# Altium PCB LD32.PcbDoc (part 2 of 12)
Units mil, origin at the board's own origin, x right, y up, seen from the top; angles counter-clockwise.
Board outline 7007.87 x 4368.85 mil, 12 copper layers (Top Layer, Int1 (GND), Int2 (AVDD), Int3 (DVDD), Int4 (GND), Int5 (ST), Int6 (SB), Int8 (AGND), Int7 (AVCC), Int9 (VCCA), Int10 (GND), Bottom Layer), stack 60.136 mil thick; 1165 components, 667 nets, 3910 pads, 2570 vias.
Unrouted connection lines stored in the file: 14.
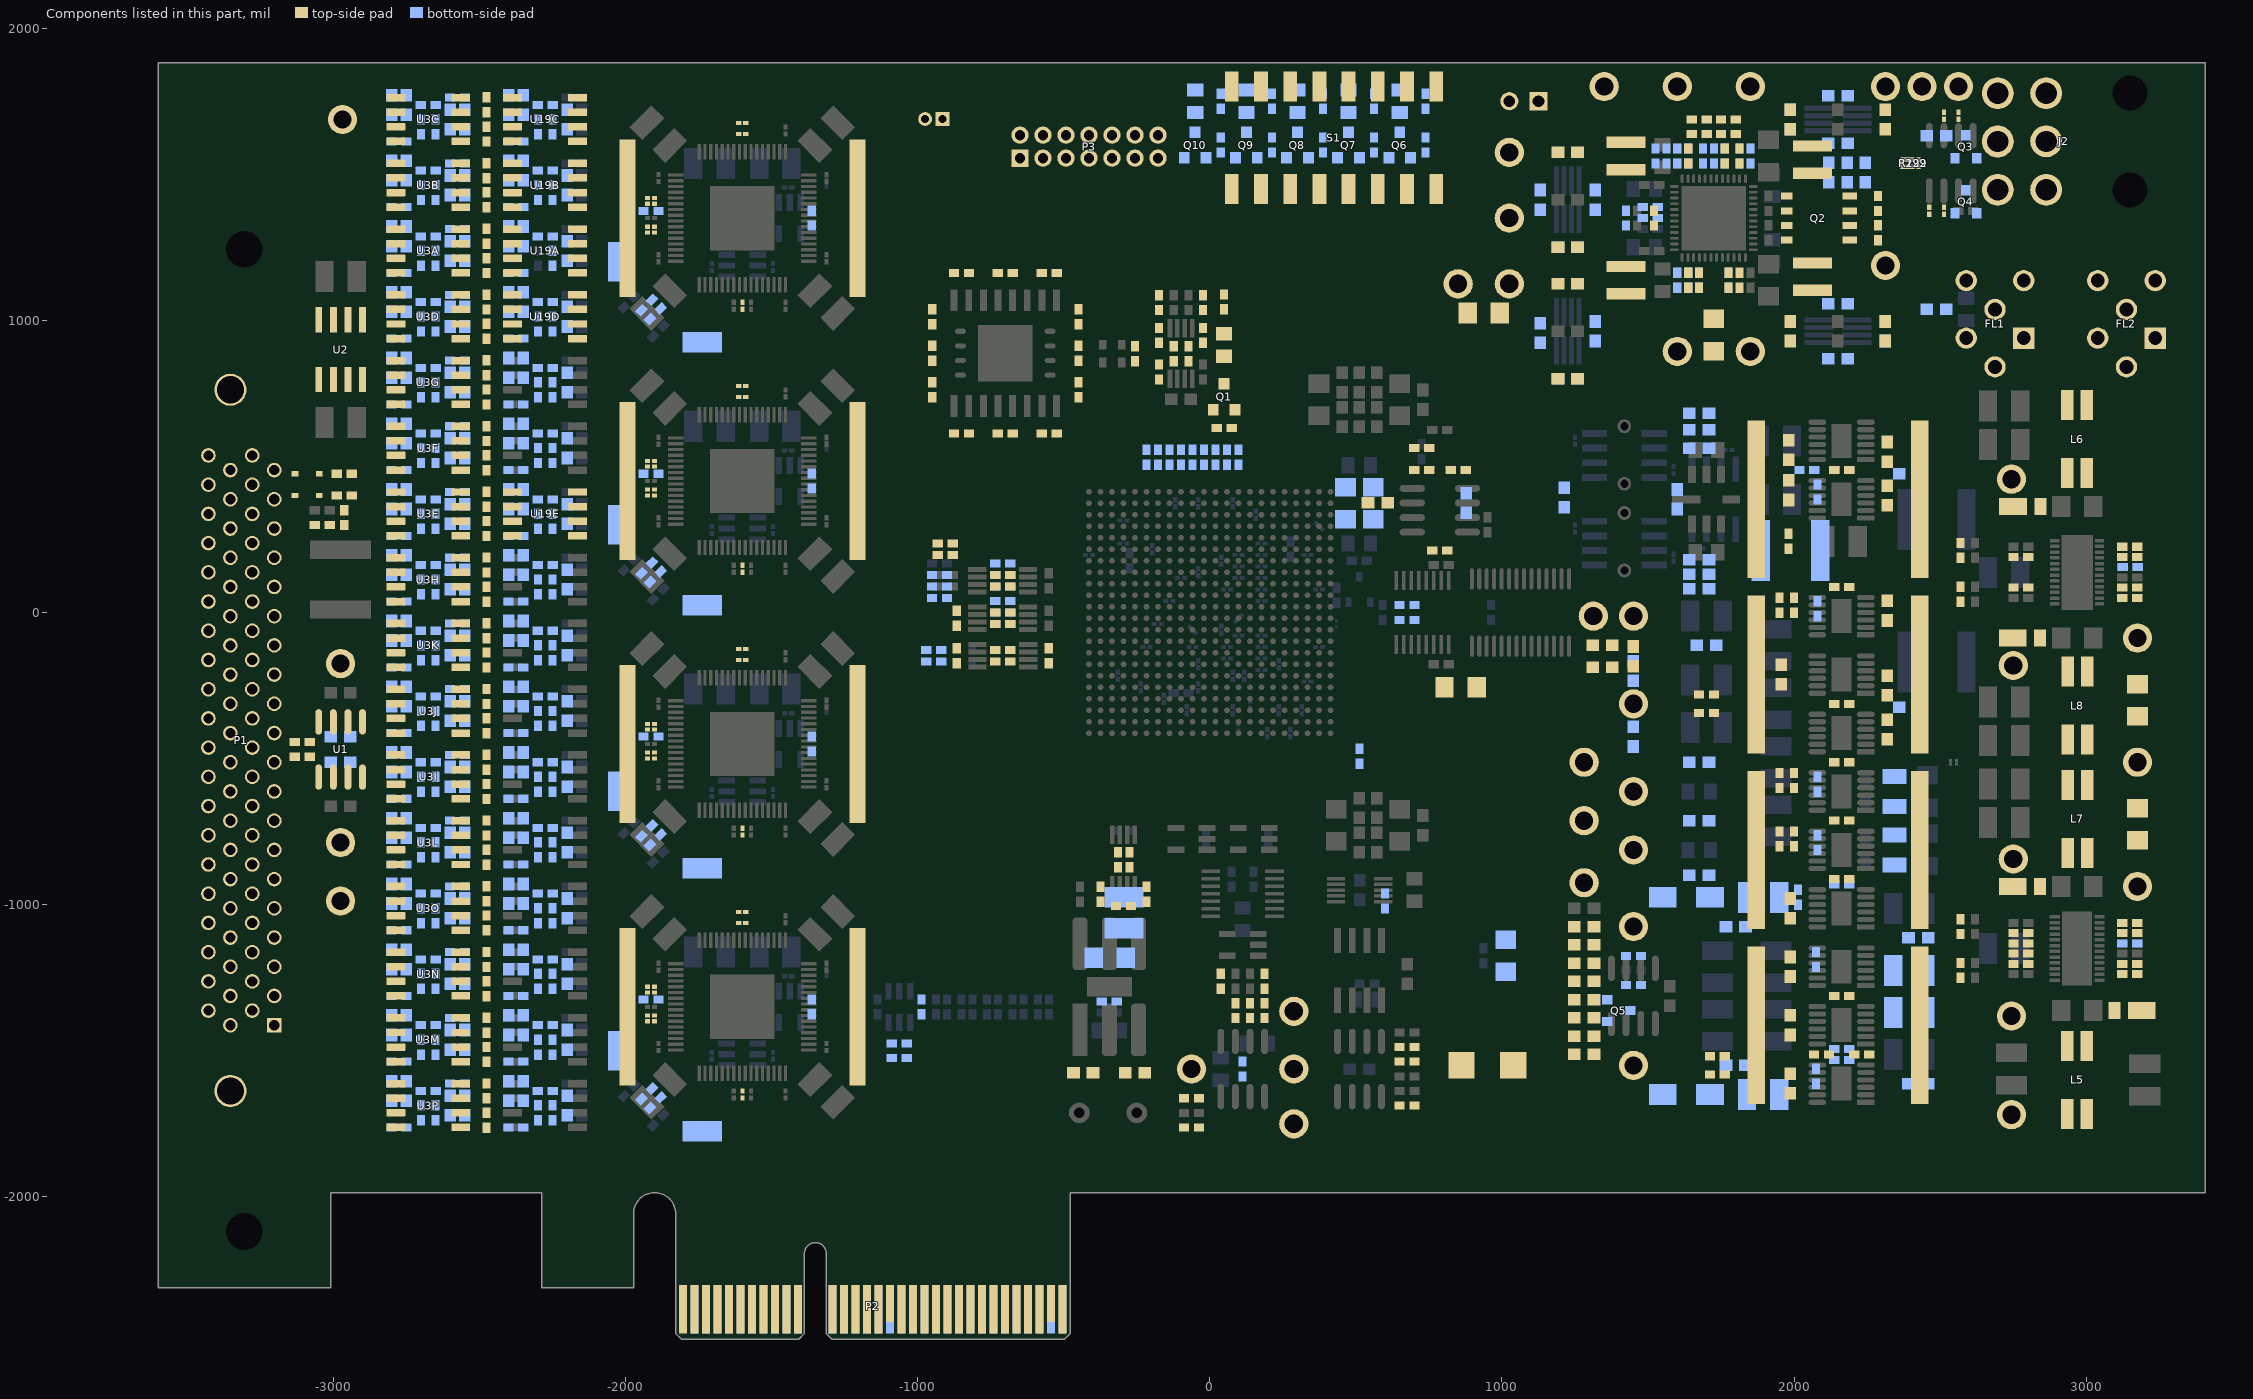
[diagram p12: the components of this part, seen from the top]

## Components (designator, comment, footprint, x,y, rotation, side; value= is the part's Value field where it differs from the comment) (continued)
C351B "NL" CC1005-0402 -2300,1437.5 r270 bottom locked (schematic designator C351)
C351C "NL" CC1005-0402 -2300,1662.5 r270 bottom locked (schematic designator C351)
C351D "NL" CC1005-0402 -2300,987.5 r270 bottom locked (schematic designator C351)
C351E "NL" CC1005-0402 -2300,312.5 r270 bottom locked (schematic designator C351)
C351F "NL" CC1005-0402 -2300,537.5 r270 bottom locked (schematic designator C351)
C351G "NL" CC1005-0402 -2300,762.5 r270 bottom locked (schematic designator C351)
C351H "NL" CC1005-0402 -2300,87.5 r270 bottom locked (schematic designator C351)
C351I "NL" CC1005-0402 -2300,-587.5 r270 bottom locked (schematic designator C351)
C351J "NL" CC1005-0402 -2300,-362.5 r270 bottom locked (schematic designator C351)
C351K "NL" CC1005-0402 -2300,-137.5 r270 bottom locked (schematic designator C351)
C351L "NL" CC1005-0402 -2300,-812.5 r270 bottom locked (schematic designator C351)
C351M "NL" CC1005-0402 -2300,-1487.5 r270 bottom locked (schematic designator C351)
C351N "NL" CC1005-0402 -2300,-1262.5 r270 bottom locked (schematic designator C351)
C351O "NL" CC1005-0402 -2300,-1037.5 r270 bottom locked (schematic designator C351)
C351P "NL" CC1005-0402 -2300,-1712.5 r270 bottom locked (schematic designator C351)
C367A "100nF" CC1005-0402 -2375,1162.5 r0 bottom locked (schematic designator C367)
C367B "100nF" CC1005-0402 -2375,1387.5 r0 bottom locked (schematic designator C367)
C367C "100nF" CC1005-0402 -2375,1612.5 r0 bottom locked (schematic designator C367)
C367D "100nF" CC1005-0402 -2375,937.5 r0 bottom locked (schematic designator C367)
C367E "100nF" CC1005-0402 -2375,262.5 r0 bottom locked (schematic designator C367)
C367F "100nF" CC1005-0402 -2375,487.5 r0 bottom locked (schematic designator C367)
C367G "100nF" CC1005-0402 -2375,712.5 r0 bottom locked (schematic designator C367)
C367H "100nF" CC1005-0402 -2375,37.5 r0 bottom locked (schematic designator C367)
C367I "100nF" CC1005-0402 -2375,-637.5 r0 bottom locked (schematic designator C367)
C367J "100nF" CC1005-0402 -2375,-412.5 r0 bottom locked (schematic designator C367)
C367K "100nF" CC1005-0402 -2375,-187.5 r0 bottom locked (schematic designator C367)
C367L "100nF" CC1005-0402 -2375,-862.5 r0 bottom locked (schematic designator C367)
C367M "100nF" CC1005-0402 -2375,-1537.5 r0 bottom locked (schematic designator C367)
C367N "100nF" CC1005-0402 -2375,-1312.5 r0 bottom locked (schematic designator C367)
C367O "100nF" CC1005-0402 -2375,-1087.5 r0 bottom locked (schematic designator C367)
C367P "100nF" CC1005-0402 -2375,-1762.5 r0 bottom locked (schematic designator C367)
C383A "2.2nF" CC1608-0603 -2400,1287.5 r270 bottom locked (schematic designator C383)
C383B "2.2nF" CC1608-0603 -2400,1512.5 r270 bottom locked (schematic designator C383)
C383C "2.2nF" CC1608-0603 -2400,1737.5 r270 bottom locked (schematic designator C383)
C383D "2.2nF" CC1608-0603 -2400,1062.5 r270 bottom locked (schematic designator C383)
C383E "2.2nF" CC1608-0603 -2400,387.5 r270 bottom locked (schematic designator C383)
C383F "2.2nF" CC1608-0603 -2400,612.5 r270 bottom locked (schematic designator C383)
C383G "2.2nF" CC1608-0603 -2400,837.5 r270 bottom locked (schematic designator C383)
C383H "2.2nF" CC1608-0603 -2400,162.5 r270 bottom locked (schematic designator C383)
C383I "2.2nF" CC1608-0603 -2400,-512.5 r270 bottom locked (schematic designator C383)
C383J "2.2nF" CC1608-0603 -2400,-287.5 r270 bottom locked (schematic designator C383)
C383K "2.2nF" CC1608-0603 -2400,-62.5 r270 bottom locked (schematic designator C383)
C383L "2.2nF" CC1608-0603 -2400,-737.5 r270 bottom locked (schematic designator C383)
C383M "2.2nF" CC1608-0603 -2400,-1412.5 r270 bottom locked (schematic designator C383)
C383N "2.2nF" CC1608-0603 -2400,-1187.5 r270 bottom locked (schematic designator C383)
C383O "2.2nF" CC1608-0603 -2400,-962.5 r270 bottom locked (schematic designator C383)
C383P "2.2nF" CC1608-0603 -2400,-1637.5 r270 bottom locked (schematic designator C383)
C399A "2.2nF" CC1608-0603 -2550,1237.5 r270 bottom locked (schematic designator C399)
C399B "2.2nF" CC1608-0603 -2550,1462.5 r270 bottom locked (schematic designator C399)
C399C "2.2nF" CC1608-0603 -2550,1687.5 r270 bottom locked (schematic designator C399)
C399D "2.2nF" CC1608-0603 -2550,1012.5 r270 bottom locked (schematic designator C399)
C399E "2.2nF" CC1608-0603 -2550,337.5 r270 bottom locked (schematic designator C399)
C399F "2.2nF" CC1608-0603 -2550,562.5 r270 bottom locked (schematic designator C399)
C399G "2.2nF" CC1608-0603 -2550,787.5 r270 bottom locked (schematic designator C399)
C399H "2.2nF" CC1608-0603 -2550,112.5 r270 bottom locked (schematic designator C399)
C399I "2.2nF" CC1608-0603 -2550,-562.5 r270 bottom locked (schematic designator C399)
C399J "2.2nF" CC1608-0603 -2550,-337.5 r270 bottom locked (schematic designator C399)
C399K "2.2nF" CC1608-0603 -2550,-112.5 r270 bottom locked (schematic designator C399)
C399L "2.2nF" CC1608-0603 -2550,-787.5 r270 bottom locked (schematic designator C399)
C399M "2.2nF" CC1608-0603 -2550,-1462.5 r270 bottom locked (schematic designator C399)
C399N "2.2nF" CC1608-0603 -2550,-1237.5 r270 bottom locked (schematic designator C399)
C399O "2.2nF" CC1608-0603 -2550,-1012.5 r270 bottom locked (schematic designator C399)
C399P "2.2nF" CC1608-0603 -2550,-1687.5 r270 bottom locked (schematic designator C399)
C415A "100nF" CC1005-0402 -2575,1312.5 r180 bottom locked (schematic designator C415)
C415B "100nF" CC1005-0402 -2575,1537.5 r180 bottom locked (schematic designator C415)
C415C "100nF" CC1005-0402 -2575,1762.5 r180 bottom locked (schematic designator C415)
C415D "100nF" CC1005-0402 -2575,1087.5 r180 bottom locked (schematic designator C415)
C415E "100nF" CC1005-0402 -2575,412.5 r180 bottom locked (schematic designator C415)
C415F "100nF" CC1005-0402 -2575,637.5 r180 bottom locked (schematic designator C415)
C415G "100nF" CC1005-0402 -2575,862.5 r180 bottom locked (schematic designator C415)
C415H "100nF" CC1005-0402 -2575,187.5 r180 bottom locked (schematic designator C415)
C415I "100nF" CC1005-0402 -2575,-487.5 r180 bottom locked (schematic designator C415)
C415J "100nF" CC1005-0402 -2575,-262.5 r180 bottom locked (schematic designator C415)
C415K "100nF" CC1005-0402 -2575,-37.5 r180 bottom locked (schematic designator C415)
C415L "100nF" CC1005-0402 -2575,-712.5 r180 bottom locked (schematic designator C415)
C415M "100nF" CC1005-0402 -2575,-1387.5 r180 bottom locked (schematic designator C415)
C415N "100nF" CC1005-0402 -2575,-1162.5 r180 bottom locked (schematic designator C415)
C415O "100nF" CC1005-0402 -2575,-937.5 r180 bottom locked (schematic designator C415)
C415P "100nF" CC1005-0402 -2575,-1612.5 r180 bottom locked (schematic designator C415)
C431A "NL" CC1005-0402 -2700,1212.5 r270 bottom locked (schematic designator C431)
C431B "NL" CC1005-0402 -2700,1437.5 r270 bottom locked (schematic designator C431)
C431C "NL" CC1005-0402 -2700,1662.5 r270 bottom locked (schematic designator C431)
C431D "NL" CC1005-0402 -2700,987.5 r270 bottom locked (schematic designator C431)
C431E "NL" CC1005-0402 -2700,312.5 r270 bottom locked (schematic designator C431)
C431F "NL" CC1005-0402 -2700,537.5 r270 bottom locked (schematic designator C431)
C431G "NL" CC1005-0402 -2700,762.5 r270 bottom locked (schematic designator C431)
C431H "NL" CC1005-0402 -2700,87.5 r270 bottom locked (schematic designator C431)
C431I "NL" CC1005-0402 -2700,-587.5 r270 bottom locked (schematic designator C431)
C431J "NL" CC1005-0402 -2700,-362.5 r270 bottom locked (schematic designator C431)
C431K "NL" CC1005-0402 -2700,-137.5 r270 bottom locked (schematic designator C431)
C431L "NL" CC1005-0402 -2700,-812.5 r270 bottom locked (schematic designator C431)
C431M "NL" CC1005-0402 -2700,-1487.5 r270 bottom locked (schematic designator C431)
C431N "NL" CC1005-0402 -2700,-1262.5 r270 bottom locked (schematic designator C431)
C431O "NL" CC1005-0402 -2700,-1037.5 r270 bottom locked (schematic designator C431)
C431P "NL" CC1005-0402 -2700,-1712.5 r270 bottom locked (schematic designator C431)
C447A "100nF" CC1005-0402 -2775,1162.5 r0 bottom locked (schematic designator C447)
C447B "100nF" CC1005-0402 -2775,1387.5 r0 bottom locked (schematic designator C447)
C447C "100nF" CC1005-0402 -2775,1612.5 r0 bottom locked (schematic designator C447)
C447D "100nF" CC1005-0402 -2775,937.5 r0 bottom locked (schematic designator C447)
C447E "100nF" CC1005-0402 -2775,262.5 r0 bottom locked (schematic designator C447)
C447F "100nF" CC1005-0402 -2775,487.5 r0 bottom locked (schematic designator C447)
C447G "100nF" CC1005-0402 -2775,712.5 r0 bottom locked (schematic designator C447)
C447H "100nF" CC1005-0402 -2775,37.5 r0 bottom locked (schematic designator C447)
C447I "100nF" CC1005-0402 -2775,-637.5 r0 bottom locked (schematic designator C447)
C447J "100nF" CC1005-0402 -2775,-412.5 r0 bottom locked (schematic designator C447)
C447K "100nF" CC1005-0402 -2775,-187.5 r0 bottom locked (schematic designator C447)
C447L "100nF" CC1005-0402 -2775,-862.5 r0 bottom locked (schematic designator C447)
C447M "100nF" CC1005-0402 -2775,-1537.5 r0 bottom locked (schematic designator C447)
C447N "100nF" CC1005-0402 -2775,-1312.5 r0 bottom locked (schematic designator C447)
C447O "100nF" CC1005-0402 -2775,-1087.5 r0 bottom locked (schematic designator C447)
C447P "100nF" CC1005-0402 -2775,-1762.5 r0 bottom locked (schematic designator C447)
C463A "2.2nF" CC1608-0603 -2800,1287.5 r270 bottom locked (schematic designator C463)
C463B "2.2nF" CC1608-0603 -2800,1512.5 r270 bottom locked (schematic designator C463)
C463C "2.2nF" CC1608-0603 -2800,1737.5 r270 bottom locked (schematic designator C463)
C463D "2.2nF" CC1608-0603 -2800,1062.5 r270 bottom locked (schematic designator C463)
C463E "2.2nF" CC1608-0603 -2800,387.5 r270 bottom locked (schematic designator C463)
C463F "2.2nF" CC1608-0603 -2800,612.5 r270 bottom locked (schematic designator C463)
C463G "2.2nF" CC1608-0603 -2800,837.5 r270 bottom locked (schematic designator C463)
C463H "2.2nF" CC1608-0603 -2800,162.5 r270 bottom locked (schematic designator C463)
C463I "2.2nF" CC1608-0603 -2800,-512.5 r270 bottom locked (schematic designator C463)
C463J "2.2nF" CC1608-0603 -2800,-287.5 r270 bottom locked (schematic designator C463)
C463K "2.2nF" CC1608-0603 -2800,-62.5 r270 bottom locked (schematic designator C463)
C463L "2.2nF" CC1608-0603 -2800,-737.5 r270 bottom locked (schematic designator C463)
C463M "2.2nF" CC1608-0603 -2800,-1412.5 r270 bottom locked (schematic designator C463)
C463N "2.2nF" CC1608-0603 -2800,-1187.5 r270 bottom locked (schematic designator C463)
C463O "2.2nF" CC1608-0603 -2800,-962.5 r270 bottom locked (schematic designator C463)
C463P "2.2nF" CC1608-0603 -2800,-1637.5 r270 bottom locked (schematic designator C463)
C479 "1.0uF" CC1608-0603 -2975,-425 r180 bottom
C480 "1.0uF" CC1608-0603 -2975,-512.5 r0 bottom
C481 "10uF" CC3225-1210 1893.75,-1650 r180 bottom value=10uf
C482 "10uF" CC3225-1210 1893.75,-975 r0 bottom value=10uf
C483 "10uF" CC3225-1210 2393.75,-1368.75 r180 bottom value=10uf
C484 "10uF" CC3225-1210 2393.75,-1225 r0 bottom value=10uf
C500 "22uF" CC5650-2220 1987.5,212.5 r0 bottom value="22uF Film"
D1 "BAV116WSQ-7" FP-SOD323-MFG -3090,400 r0 top value=1.5pF
D2 "BAV116WSQ-7" FP-SOD323-MFG -3090,475 r180 top value=1.5pF
D3 "Schottky SMB" DO-SMB 950,-1550 r0 top
D4 "Schottky DO-PowerDI123" DO-PowerDI123 2781.25,-937.5 r180 top
D5 "Schottky DO-PowerDI123" DO-PowerDI123 2781.25,-87.5 r180 top
D6 "Schottky DO-PowerDI123" DO-PowerDI123 2782.5,362.5 r180 top
D7 "Schottky DO-PowerDI123" DO-PowerDI123 3156.25,-1362.5 r0 top
D8 "shottky diode" DO-SMA 1631.25,-975 r180 bottom
D9 "shottky diode" DO-SMA 1631.25,-1650 r0 bottom
DS1 "DONE" LED-0805 49.21,915.35 r90 top
DS2 "LED" LED-0805 650,1750 r90 bottom
DS3 "LED" LED-0805 475,1750 r90 bottom
DS4 "LED" LED-0805 300,1750 r90 bottom
DS5 "LED" LED-0805 125,1750 r90 bottom
DS6 "LED" LED-0805 -50,1750 r90 bottom
FL1 "BNX016-01" FP-BNX_L12MM2_W11MM2_T8MM-MFG 2687.5,1037.5 r270 top
FL2 "BNX016-01" FP-BNX_L12MM2_W11MM2_T8MM-MFG 3137.5,1037.5 r270 top
FR1 "BLM31PG121" CC3216-1206 858.27,-255.91 r0 top
FR2 "BLM31PG121" CC3216-1206 937.5,1025 r180 top
FR3 "BLM31PG121" CC3216-1206 1725,950 r270 top
FR4 "BLM31PG121" CC3216-1206 3175,-725 r270 top
FR5 "BLM31PG121" CC3216-1206 3175,-300 r90 top
FR6 "BLM31PG121" CC3216-1206 1012.5,-1175 r90 bottom
FR7 "BLM31PG121" CC3216-1206 559.06,374.02 r270 bottom
FR8 "BLM31PG121" CC3216-1206 464.57,374.02 r270 bottom
FR9 "BLM31PG121" CC3216-1206 -342.5,-1181.25 r0 bottom
J1 "S2B-ZR(LF)(SN)" FP-S2B-ZR_LF_SN-MFG -944.88,1751.97 r180 top
J2 "45558-0003" 455580003 2862.5,1777.5 r270 top
L1 "XFL4020-222MEC" FP-XFL4020-MFG 1425,1137.5 r270 top
L2 "XFL4020-222MEC" FP-XFL4020-MFG 1425,1562.5 r90 top
L3 "XFL4020-332MEC" FP-XFL4020-MFG 2062.5,1150 r270 top
L4 "XFL4020-472" FP-XAL40-MFG 2062.5,1550 r90 top value=4.7uH
L5 "8.2uH" MSD7342 2935.25,-1493.5 r0 top
L6 "8.2uH" MSD7342 3002.25,487.25 r180 top
L7 "8.2uH" MSD7342 3002.75,-812.75 r180 top
L8 "4.7uH" MSD7342 2935.75,-212.25 r0 top
L9 "33nH" CL2520-1008 2343.75,-812.5 r270 bottom
L10 "33nH" CL2520-1008 2343.75,-612.5 r270 bottom
LOGO1 "LIGO logo" LIGO-LOGO-SM -3415,1728.75 r0 top value=NL
MP4A "DA-T268-301E-TR" FP-DA-T268-301E-TR-MFG -1600,-1350 r0 top locked (schematic designator MP4)
MP4B "DA-T268-301E-TR" FP-DA-T268-301E-TR-MFG -1600,-450 r0 top locked (schematic designator MP4)
MP4C "DA-T268-301E-TR" FP-DA-T268-301E-TR-MFG -1600,450 r0 top locked (schematic designator MP4)
MP4D "DA-T268-301E-TR" FP-DA-T268-301E-TR-MFG -1600,1350 r0 top locked (schematic designator MP4)
MP5 "DA-T263-201E-TR" FP-DA-T263-201E-TR-MFG 2150,-1412.5 r0 top locked
MP6 "DA-T263-201E-TR" FP-DA-T263-201E-TR-MFG 2150,-812.5 r0 top
MP7 "DA-T263-201E-TR" FP-DA-T263-201E-TR-MFG 2150,-212.5 r0 top locked
MP8 "DA-T263-201E-TR" FP-DA-T263-201E-TR-MFG 2150,387.5 r0 top locked
P1 "P50E-080P1-RR1EA" P50E-080-SR1 -3302.3,-1437.5 r270 top locked
P2 "PCIeX4-GF-2D-1000-1K-O64" PCIeX4-GF-2D-1000-1K-O64 -1429.06,-2385 r0 top value=NL
P3 "2mm Header 2x7" 2MM_HDR2X7_RA -649.61,1555.12 r0 top
P4 "Header 2" WM4200 1125,1750 r180 top
Q1 "FDV301N" SO-G3/C2.25 49.21,738.19 r0 top
Q2 "SI7904BDN-T1-E3" VISH-POWERPAKSO-8_A_V 2085.04,1350 r180 top
Q3 "MMBT3906LT1G" ONSC-SOT-23-3-318-08_V 2587.5,1593.75 r90 bottom
Q4 "MMBT3906LT1G" ONSC-SOT-23-3-318-08_V 2587.5,1406.25 r90 bottom
Q5 "MMBT3906LT1G" ONSC-SOT-23-3-318-08_V 1400,-1362.5 r0 bottom
Q6 "FDV301N" SO-G3/C2.25 650,1600 r180 bottom
Q7 "FDV301N" SO-G3/C2.25 475,1600 r180 bottom
Q8 "FDV301N" SO-G3/C2.25 300,1600 r180 bottom
Q9 "FDV301N" SO-G3/C2.25 125,1600 r180 bottom
Q10 "FDV301N" SO-G3/C2.25 -50,1600 r180 bottom
R1 "100" CR1005-0402 -3106.25,-493.75 r180 top
R2 "100" CR1005-0402 -3106.25,-443.75 r180 top
R3 "10k" CR1005-0402 -3037.5,300 r180 top
R4 "1.33k" CR1005-0402 -2962.5,400 r180 top
R5 "13.3k" CR1005-0402 -2962.5,475 r180 top
R6 "1.0k" CR1005-0402 -2962.5,325 r90 top
R7A "NL" CR1005-0402 -2475,1187.5 r270 top locked (schematic designator R7)
R7B "NL" CR1005-0402 -2475,1412.5 r270 top locked (schematic designator R7)
R7C "NL" CR1005-0402 -2475,1637.5 r270 top locked (schematic designator R7)
R7D "NL" CR1005-0402 -2475,962.5 r270 top locked (schematic designator R7)
R7E "NL" CR1005-0402 -2475,287.5 r270 top locked (schematic designator R7)
R7F "NL" CR1005-0402 -2475,512.5 r270 top locked (schematic designator R7)
R7G "NL" CR1005-0402 -2475,737.5 r270 top locked (schematic designator R7)
R7H "NL" CR1005-0402 -2475,62.5 r270 top locked (schematic designator R7)
R7I "NL" CR1005-0402 -2475,-612.5 r270 top locked (schematic designator R7)
R7J "NL" CR1005-0402 -2475,-387.5 r270 top locked (schematic designator R7)
R7K "NL" CR1005-0402 -2475,-162.5 r270 top locked (schematic designator R7)
R7L "NL" CR1005-0402 -2475,-837.5 r270 top locked (schematic designator R7)
R7M "NL" CR1005-0402 -2475,-1512.5 r270 top locked (schematic designator R7)
R7N "NL" CR1005-0402 -2475,-1287.5 r270 top locked (schematic designator R7)
R7O "NL" CR1005-0402 -2475,-1062.5 r270 top locked (schematic designator R7)
R7P "NL" CR1005-0402 -2475,-1737.5 r270 top locked (schematic designator R7)
R8A "NL" CR1005-0402 -2475,1287.5 r270 top locked (schematic designator R8)
R8B "NL" CR1005-0402 -2475,1512.5 r270 top locked (schematic designator R8)
R8C "NL" CR1005-0402 -2475,1737.5 r270 top locked (schematic designator R8)
R8D "NL" CR1005-0402 -2475,1062.5 r270 top locked (schematic designator R8)
R8E "NL" CR1005-0402 -2475,387.5 r270 top locked (schematic designator R8)
R8F "NL" CR1005-0402 -2475,612.5 r270 top locked (schematic designator R8)
R8G "NL" CR1005-0402 -2475,837.5 r270 top locked (schematic designator R8)
R8H "NL" CR1005-0402 -2475,162.5 r270 top locked (schematic designator R8)
R8I "NL" CR1005-0402 -2475,-512.5 r270 top locked (schematic designator R8)
R8J "NL" CR1005-0402 -2475,-287.5 r270 top locked (schematic designator R8)
R8K "NL" CR1005-0402 -2475,-62.5 r270 top locked (schematic designator R8)
R8L "NL" CR1005-0402 -2475,-737.5 r270 top locked (schematic designator R8)
R8M "NL" CR1005-0402 -2475,-1412.5 r270 top locked (schematic designator R8)
R8N "NL" CR1005-0402 -2475,-1187.5 r270 top locked (schematic designator R8)
R8O "NL" CR1005-0402 -2475,-962.5 r270 top locked (schematic designator R8)
R8P "NL" CR1005-0402 -2475,-1637.5 r270 top locked (schematic designator R8)
R39A "47K" CR0603-0201 -1912.5,1300.79 r180 top locked (schematic designator R39)
R39B "47K" CR0603-0201 -1912.5,400.79 r180 top locked (schematic designator R39)
R39C "47K" CR0603-0201 -1912.5,-499.21 r180 top locked (schematic designator R39)
R39D "47K" CR0603-0201 -1912.5,-1399.21 r180 top locked (schematic designator R39)
R40A "47K" CR0603-0201 -1912.5,1320.47 r180 top locked (schematic designator R40)
R40B "47K" CR0603-0201 -1912.5,420.47 r180 top locked (schematic designator R40)
R40C "47K" CR0603-0201 -1912.5,-479.53 r180 top locked (schematic designator R40)
R40D "47K" CR0603-0201 -1912.5,-1379.53 r180 top locked (schematic designator R40)
R41A "2k" CR0603-0201 -1912.5,1399.21 r180 top locked (schematic designator R41)
R41B "2k" CR0603-0201 -1912.5,499.21 r180 top locked (schematic designator R41)
R41C "2k" CR0603-0201 -1912.5,-400.79 r180 top locked (schematic designator R41)
R41D "2k" CR0603-0201 -1912.5,-1300.79 r180 top locked (schematic designator R41)
R42A "2k" CR0603-0201 -1912.5,1418.9 r180 top locked (schematic designator R42)
R42B "2k" CR0603-0201 -1912.5,518.9 r180 top locked (schematic designator R42)
R42C "2k" CR0603-0201 -1912.5,-381.1 r180 top locked (schematic designator R42)
R42D "2k" CR0603-0201 -1912.5,-1281.1 r180 top locked (schematic designator R42)
R55A "100K" CR0603-0201 -1600,1637.5 r0 top locked value=100k (schematic designator R55)
R55B "100K" CR0603-0201 -1600,737.5 r0 top locked value=100k (schematic designator R55)
R55C "100K" CR0603-0201 -1600,-162.5 r0 top locked value=100k (schematic designator R55)
R55D "100K" CR0603-0201 -1600,-1062.5 r0 top locked value=100k (schematic designator R55)
R56A "NS" CR0603-0201 -1600,1675 r180 top locked (schematic designator R56)
R56B "NS" CR0603-0201 -1600,775 r180 top locked (schematic designator R56)
R56C "NS" CR0603-0201 -1600,-125 r180 top locked (schematic designator R56)
R56D "NS" CR0603-0201 -1600,-1025 r180 top locked (schematic designator R56)
R63A "100K" CR0603-0201 -1600,1050 r90 top value=100k (schematic designator R63)
R63B "100K" CR0603-0201 -1600,150 r90 top value=100k (schematic designator R63)
R63C "100K" CR0603-0201 -1600,-750 r90 top value=100k (schematic designator R63)
R63D "100K" CR0603-0201 -1600,-1650 r90 top value=100k (schematic designator R63)
R67 "1.8k" CR1005-0402 -950,762.5 r270 top locked
R68 "1.8k" CR1005-0402 -950,887.5 r270 top locked
R69 "NL" CR1005-0402 -950,1012.5 r270 top locked
R70 "NL" CR1005-0402 -905.51,196.85 r180 top
R71 "1.0k" CR1005-0402 -905.51,236.22 r180 top
R72 "100" CR1005-0402 -850,612.5 r0 top locked
R73 "NL" CR1005-0402 -850,1162.5 r0 top locked
R74 "NL" CR1005-0402 -866.14,-147.64 r90 top locked
R75 "100" CR1005-0402 -866.14,-19.68 r270 top
R76 "NL" CR1005-0402 -708.66,-167.32 r180 top
R77 "NL" CR1005-0402 -708.66,-127.95 r180 top
R78 "NL" CR1005-0402 -708.66,-39.37 r0 top
R79 "NL" CR1005-0402 -708.66,0 r0 top
R80 "NL" CR1005-0402 -708.66,88.58 r0 top
R81 "NL" CR1005-0402 -708.66,127.95 r0 top
R82 "1.8k" CR1005-0402 -700,612.5 r0 top
R83 "100" CR1005-0402 -700,1162.5 r0 top
R84 "100" CR1005-0402 -550,1162.5 r180 top
R85 "4.7k" CR1005-0402 -550,612.5 r0 top
R86 "100" CR1005-0402 -551.18,-147.64 r90 top
R87 "NL" CR1608-0603 -433.07,-1574.8 r180 top
R88 "1.8k" CR1005-0402 -450,762.5 r270 top
R89 "100" CR1005-0402 -450,887.5 r90 top
R90 "1.8k" CR1005-0402 -450,1012.5 r90 top
R91 "NL" CR1005-0402 -374.02,-964.57 r270 top
R92 "NL" CR1005-0402 -295.28,-1003.94 r0 top
R93 "NL" CR1005-0402 -314.96,-846.46 r270 top
R94 "NL" CR1608-0603 -255.91,-1574.8 r0 top
R95 "NL" CR1005-0402 -275.59,-846.46 r90 top
R96 "4.7k" CR1005-0402 -255.91,885.83 r90 top
R97 "NL" CR1005-0402 -216.54,-964.57 r90 top
R98 "22K" CR1005-0402 -173.43,823.33 r270 top
R99 "49.9" CR1005-0402 -173.43,948.33 r90 top
R100 "2.32K" CR1005-0402 -173.43,1060.83 r90 top
R101 "NL" CR1005-0402 -123.43,885.83 r270 top
R102 "10k" CR1005-0402 -62.5,-1662.5 r180 top
R103 "1.0K" CR1005-0402 -62.5,-1762.5 r0 top value=1.0k
R104 "NL" CR1005-0402 -73.43,885.83 r270 top
R105 "49.9" CR1005-0402 -23.43,948.33 r270 top
R106 "1.6K" CR1005-0402 -23.43,1060.83 r270 top
R107 "4.7k" CR1005-0402 49.21,631.76 r0 top
R108 "10K" CR1005-0402 37.5,-1262.5 r270 top value=10k
R109 "1.0k" CR1005-0402 49.21,1062.99 r270 top
R110 "10K" CR1005-0402 87.5,-1362.5 r270 top value=10k
R111 "10K" CR1005-0402 137.5,-1362.5 r270 top value=10k
R112 "20K" CR1005-0402 187.5,-1362.5 r270 top
R113 "10K" CR1005-0402 187.5,-1262.5 r270 top value=10k
R114 "1k" CR1608-0603 575,375 r0 top
R115 "20K" CR1005-0402 675,-1687.5 r180 top
R116 "10K" CR1005-0402 675,-1537.5 r0 top value=10k
R117 "10K" CR1005-0402 675,-1487.5 r0 top value=10k
R118 "100K" CR1005-0402 725,562.5 r180 top
R119 "2.0k" CR1005-0402 725,487.5 r0 top
R120 "2.0k" CR1005-0402 787.5,212.5 r0 top
R121 "100K" CR1005-0402 850,487.5 r0 top
R122 "220" CR1608-0603 1225,800 r180 top
R123 "10k" CR1608-0603 1225,800 r0 bottom
R124 "100" CR1608-0603 1318.75,962.5 r90 bottom
R125 "100" CR1608-0603 1318.75,1412.5 r90 bottom
R126 "220" CR1608-0603 1225,1250 r180 top
R127 "10k" CR1608-0603 1225,1250 r0 bottom
R128 "10m" CR1608-0603 1225,1125 r0 top
R129 "10m" CR1608-0603 1225,1575 r0 top
R130 "1.37k" CR1608-0603 1281.25,-1387.5 r180 top
R131 "220" CR1608-0603 1281.25,-1325 r180 top
R132 "220" CR1608-0603 1281.25,-1262.5 r180 top
R133 "220" CR1608-0603 1281.25,-1200 r180 top
R134 "59k" CR1608-0603 1281.25,-1137.5 r180 top
R135 "1k" CR1608-0603 1281.25,-1075 r180 top
R136 "3.7k" CR1608-0603 1281.25,-1450 r0 top
R137 "1k" CR1608-0603 1343.75,-187.5 r180 top
R138 "59k" CR1608-0603 1450,-150 r270 top
R139 "220" CR1608-0603 1343.75,-112.5 r180 top
R140 "59k" CR1608-0603 1281.25,-1512.5 r0 top
R141 "3.44k" CR1608-0603 1131.25,956.25 r90 bottom
R142 "3.44k" CR1608-0603 1131.25,1412.5 r90 bottom
R143 "1.0k" CR1005-0402 1737.5,-1581.25 r180 top
R144 "4.99k" CR1005-0402 1520,1350 r270 top
R145 "15k" CR1005-0402 1637.5,1137.5 r90 top
R146 "9.31k" CR1005-0402 1637.5,1562.5 r270 top
R147 "21.5k" CR1005-0402 1675,1687.5 r180 top
R148 "10k" CR1005-0402 1675,1637.5 r0 top
R149 "49.9k" CR1005-0402 1700,-343.75 r0 top
R150 "130K" CR1005-0402 1700,-281.25 r0 top
R151 "100K" CR1005-0402 2162.5,487.5 r0 bottom
R152 "100K" CR1005-0402 2043.75,487.5 r0 bottom
R153 "31.6k" CR1005-0402 1675,1137.5 r270 top
R154 "10k" CR1005-0402 1775,1637.5 r180 top
R155 "13.3k" CR1005-0402 1775,1687.5 r0 top
R156 "37.4k" CR1005-0402 1762.5,1562.5 r90 top
R157 "10k" CR1005-0402 1775,1137.5 r270 top
R158 "7.15k" CR1005-0402 1812.5,1137.5 r90 top
R159 "56.2k" CR1005-0402 1812.5,1562.5 r270 top
R160 "6.49k" CR1608-0603 1956.25,-212.5 r270 top
R161 "220" CR1608-0603 1987.5,1687.5 r90 top
R162 "130K" CR1005-0402 1950,-775 r270 top
R163 "100K" CR1005-0402 1950,-575 r270 top
R164 "100K" CR1005-0402 1950,25 r90 top
R165 "10m" CR1608-0603 1987.5,-1612.5 r270 top
R166 "10m" CR1608-0603 1987.5,-1412.5 r270 top
R167 "10m" CR1608-0603 1987.5,-1212.5 r270 top
R168 "10m" CR1608-0603 1987.5,-1012.5 r270 top
R169 "10k" CR1608-0603 1987.5,1687.5 r270 bottom
R170 "49.9K" CR1005-0402 2000,-775 r90 top value=49.9k
R171 "49.9K" CR1005-0402 2000,-575 r90 top value=49.9k
R172 "49.9k" CR1005-0402 2000,25 r270 top
R173 "10m" CR1608-0603 1987.5,962.5 r90 top
R174 "267K" CR1005-0402 2093.75,-1512.5 r180 top
R175 "3.44k" CR1608-0603 2150,1768.75 r0 bottom
R176 "100" CR1608-0603 2150,1606.25 r0 bottom
R177 "150" CR1005-0402 2162.5,-312.5 r180 top
R178 "300" CR1005-0402 2162.5,87.5 r180 top
R179 "150" CR1005-0402 2162.5,487.5 r180 top
R180 "249K" CR1005-0402 2162.5,-1312.5 r0 top
R181 "150" CR1005-0402 2162.5,-912.5 r0 top
R182 "300" CR1005-0402 2162.5,-712.5 r0 top
R183 "300" CR1005-0402 2162.5,-512.5 r0 top
R184 "3.44k" CR1608-0603 2150,868.75 r180 bottom
R185 "100" CR1608-0603 2150,1056.25 r180 bottom
R186 "150" CR1005-0402 2231.25,-1512.5 r180 top
R187 "47k" CR1005-0402 2287.5,1300 r270 top
R188 "NL" CR1005-0402 2287.5,1400 r270 top
R189 "10m" CR1608-0603 2312.5,1687.5 r270 top
R190 "10m" CR1608-0603 2318.75,-400 r90 top
R191 "10m" CR1608-0603 2318.75,-250 r270 top
R192 "10m" CR1608-0603 2318.75,6.25 r90 top
R193 "10m" CR1608-0603 2318.75,400 r90 top
R194 "10m" CR1608-0603 2318.75,550 r270 top
R195 "10k" CR1608-0603 2312.5,962.5 r90 bottom
R196 "220" CR1608-0603 2312.5,962.5 r270 top
R197 "1k" CR0603-0201 2512.5,1700 r90 top
R198 "1k" CR0603-0201 2462.5,1375 r90 top
R199 "0.01" CR0816-0306-4P 2398.75,1537.5 r270 top
R200 "1k" CR0603-0201 2562.5,1700 r90 top
R201 "100K" CR1005-0402 2568.75,-1225 r90 top
R202 "100K" CR1005-0402 2568.75,-1075 r90 top
R203 "10K" CR1005-0402 2568.75,62.5 r90 top
R204 "34.8K" CR1005-0402 2568.75,212.5 r90 top
R205 "1.0k" CR1005-0402 2776.25,-1202.5 r180 top
R206 "1.0k" CR1005-0402 2776.25,85 r180 top
R207 "14K" CR1005-0402 2776.25,-1167.5 r0 top
R208 "0" CR1005-0402 2776.25,-1132.5 r0 top
R209 "1.0k" CR1005-0402 2776.25,-1097.5 r0 top
R210 "1.0k" CR1005-0402 2776.25,190 r0 top
R211 "76.8K" CR1005-0402 3148.75,-1097.5 r180 top
R212 "76.8K" CR1005-0402 3148.75,190 r180 top
R213 "715K" CR1005-0402 3148.75,-1237.5 r0 top
R214 "76.8K" CR1005-0402 3148.75,-1202.5 r0 top
R215 "715K" CR1005-0402 3148.75,-1062.5 r0 top
R216 "715K" CR1005-0402 3148.75,50 r0 top
R217 "76.8K" CR1005-0402 3148.75,85 r0 top
R218 "715K" CR1005-0402 3148.75,225 r0 top
R219 "4.7k" CR1005-0402 3150,155 r0 bottom
R220 "4.7k" CR1005-0402 3148.75,-1132.5 r0 bottom
R221 "15k" CR1608-0603 2487.5,1631.25 r0 bottom
R222 "0.01" CR0816-0306-4P 2398.75,1537.5 r90 bottom
R223 "1k" CR0603-0201 2512.5,1375 r90 top
R224 "10m" CR1608-0603 2487.6,1037.5 r0 bottom
R225 "0" CR1608-0603 2425,-1612.5 r0 bottom
R226 "0" CR1608-0603 2425,-1112.5 r0 bottom
R227 "10m" CR1608-0603 2393.75,-325 r0 bottom
R228 "10m" CR1608-0603 2393.75,475 r0 bottom
R229 "59k" CR1608-0603 2243.75,1506.25 r270 bottom
R230 "1k" CR1608-0603 2181.25,1506.25 r90 bottom
R231 "34.4k" CR1608-0603 1675,131.25 r180 bottom
R232 "4.7k" CR1005-0402 2162.5,-1531.25 r0 bottom
R233 "100K" CR1005-0402 2162.5,-1493.75 r0 bottom
R234 "4.7k" CR1005-0402 2162.5,-931.25 r0 bottom
R235 "220" CR1608-0603 2118.75,1506.25 r90 bottom
R236 "100K" CR1005-0402 2012.5,-975 r90 bottom
R237 "12.1K" CR1005-0402 2079.44,-787.5 r90 bottom
R238 "10K" CR1005-0402 2079.44,-587.5 r90 bottom value=10k
R239 "33k" CR1005-0402 2079.44,12.5 r90 bottom
R240 "16.5k" CR1005-0402 2079.44,412.5 r90 bottom
R241 "34.8K" CR1005-0402 2075,-1587.5 r270 bottom
R242 "34.8K" CR1005-0402 2075,-1187.5 r90 bottom
R243 "48.1k" CR1608-0603 1675,181.25 r180 bottom
R244 "59.7k TF" CR1608-0603 1600,387.5 r270 bottom
R245 "48.1k" CR1608-0603 1675,625 r180 bottom
R246 "0" CR1005-0402 1850,1562.5 r270 bottom
R247 "1.0k" CR1005-0402 1737.5,-1518.75 r180 top
R248 "10m" CR1608-0603 1800,-1550 r0 bottom
R249 "10m" CR1608-0603 1800,-1075 r0 bottom
R250 "NL" CR1005-0402 1812.5,1562.5 r90 bottom
R251 "40.2k" CR1005-0402 1775,1137.5 r270 bottom
R252 "0" CR1005-0402 1762.5,1562.5 r90 bottom
R253 "220" CR1608-0603 1700,-112.5 r180 bottom
R254 "220" CR1608-0603 1675,81.25 r180 bottom
R255 "220" CR1608-0603 1675,681.25 r180 bottom
R256 "NL" CR1005-0402 1725,1562.5 r90 bottom
R257 "220" CR1608-0603 1675,-900 r180 bottom
R258 "220" CR1608-0603 1675,-712.5 r180 bottom
R259 "220" CR1608-0603 1675,-512.5 r180 bottom
R260 "NL" CR1005-0402 1687.5,1562.5 r270 bottom
R261 "10k" CR1005-0402 1675,1137.5 r270 bottom
R262 "48.1k" CR1608-0603 1675,562.5 r0 bottom
R263 "9.53k" CR1005-0402 1637.5,1137.5 r270 bottom
R264 "402k" CR1005-0402 1637.5,1562.5 r90 bottom
R265 "10k" CR1005-0402 1600,1137.5 r90 bottom
R266 "301k" CR1005-0402 1600,1562.5 r270 bottom
R267 "NL" CR1005-0402 1562.5,1562.5 r270 bottom
R268 "7.15k" CR1005-0402 1507.5,1387.5 r0 bottom
R269 "1.91k" CR1005-0402 1507.5,1350 r180 bottom
R270 "48.1k" CR1608-0603 1212.5,393.75 r90 bottom
R271 "7.15k" CR1005-0402 1525,1562.5 r90 bottom
R272 "10m" CR1608-0603 1981.25,556.25 r90 top
R273 "10m" CR1608-0603 1981.25,418.75 r90 top
R274 "30k" CR1005-0402 1450,-1275 r0 bottom
R275 "30k" CR1005-0402 1450,-1175 r180 bottom
R276 "10m" CR1608-0603 1450,-425 r90 bottom
R277 "10m" CR1608-0603 1450,-200 r90 bottom
R278 "4.7k" CR1005-0402 1425,1350 r270 bottom
R279 "1k" CR1608-0603 877.5,375 r270 bottom
R280 "4.7k" CR1005-0402 737.5,1600 r90 bottom
R281 "1.0k" CR1005-0402 737.5,1750 r90 bottom
R282 "49.9" CR1005-0402 675,-25 r180 bottom
R283 "49.9" CR1005-0402 675,25 r180 bottom
R284 "10" CR1005-0402 600,-987.5 r270 bottom
R285 "4.7k" CR1005-0402 562.5,1600 r90 bottom
R286 "1.0k" CR1005-0402 562.5,1750 r90 bottom
R287 "100" CR1005-0402 511.81,-492.13 r270 bottom
R288 "4.7k" CR1005-0402 387.5,1600 r90 bottom
R289 "1.0k" CR1005-0402 387.5,1750 r90 bottom
R290 "4.7k" CR1005-0402 212.5,1600 r90 bottom
R291 "1.0k" CR1005-0402 212.5,1750 r90 bottom
R292 "4.99K" CR1005-0402 112.5,-1562.5 r270 bottom value=4.99k
R293 "4.7k" CR1005-0402 98.43,531.5 r90 bottom
R294 "4.7k" CR1005-0402 59.06,531.5 r90 bottom
R295 "4.7k" CR1005-0402 37.5,1600 r90 bottom
R296 "1.0k" CR1005-0402 37.5,1750 r90 bottom
R297 "4.7k" CR1005-0402 19.69,531.5 r90 bottom
R298 "4.7k" CR1005-0402 -19.69,531.5 r90 bottom
R299 "100" CR1005-0402 -59.06,531.5 r270 bottom
R300 "100" CR1005-0402 -98.43,531.5 r270 bottom
R301 "100" CR1005-0402 -137.8,531.5 r270 bottom
R302 "100" CR1005-0402 -177.17,531.5 r270 bottom
R303 "1.0K" CR1005-0402 -343.75,-1331.25 r0 bottom value=1.0k
R304 "4.7k" CR1005-0402 -216.54,531.5 r90 bottom
R305 "1.6K" CR1005-0402 -708.66,-39.37 r0 bottom
R306 "NL" CR1005-0402 -708.66,39.37 r0 bottom
R307 "2.32K" CR1005-0402 -708.66,88.58 r0 bottom
R308 "2.67K" CR1005-0402 -708.66,0 r180 bottom
R309 "NL" CR1005-0402 -708.66,127.95 r180 bottom
R310 "1.6K" CR1005-0402 -708.66,167.32 r180 bottom
R311 "49.9" CR1005-0402 -925.2,88.58 r0 bottom
R312 "22K" CR1005-0402 -925.2,49.21 r180 bottom
R313 "49.9" CR1005-0402 -925.2,127.95 r180 bottom
R314 "NL" CR1005-0402 -944.88,-167.32 r0 bottom
R315 "NL" CR1005-0402 -944.88,-127.95 r180 bottom
R316 "NL" CR1005-0402 -987.5,-1350 r270 bottom
R317 "15" CR1005-0402 -1062.5,-1525 r0 bottom
R318 "NL" CR1005-0402 -1062.5,-1475 r180 bottom
R319A "100" CR1005-0402 -1362.5,1350 r90 bottom locked (schematic designator R319)
R319B "100" CR1005-0402 -1362.5,450 r90 bottom locked (schematic designator R319)
R319C "100" CR1005-0402 -1362.5,-450 r90 bottom locked (schematic designator R319)
R319D "100" CR1005-0402 -1362.5,-1350 r90 bottom (schematic designator R319)
R323A "100K" CR1005-0402 -1897.5,1022.5 r45 bottom locked (schematic designator R323)
R323B "100K" CR1005-0402 -1897.5,122.5 r45 bottom locked (schematic designator R323)
R323C "100K" CR1005-0402 -1897.5,-777.5 r45 bottom locked (schematic designator R323)
R323D "100K" CR1005-0402 -1897.5,-1677.5 r45 bottom locked (schematic designator R323)
R327A "NL" CR1005-0402 -1912.5,1375 r0 bottom (schematic designator R327)
R327B "NL" CR1005-0402 -1912.5,475 r0 bottom (schematic designator R327)
R327C "NL" CR1005-0402 -1912.5,-425 r0 bottom (schematic designator R327)
R327D "NL" CR1005-0402 -1912.5,-1325 r0 bottom (schematic designator R327)
R331A "100K" CR1005-0402 -1927.5,1052.5 r45 bottom locked (schematic designator R331)
R331B "100K" CR1005-0402 -1927.5,152.5 r45 bottom locked (schematic designator R331)
R331C "100K" CR1005-0402 -1927.5,-747.5 r45 bottom locked (schematic designator R331)
R331D "100K" CR1005-0402 -1927.5,-1647.5 r45 bottom locked (schematic designator R331)
R335A "665" CR1608-0603 -2200,1237.5 r90 bottom locked (schematic designator R335)
R335B "665" CR1608-0603 -2200,1462.5 r90 bottom locked (schematic designator R335)
R335C "665" CR1608-0603 -2200,1687.5 r90 bottom locked (schematic designator R335)
R335D "665" CR1608-0603 -2200,1012.5 r90 bottom locked (schematic designator R335)
R335E "665" CR1608-0603 -2200,337.5 r90 bottom locked (schematic designator R335)
R335F "665" CR1608-0603 -2200,562.5 r90 bottom locked (schematic designator R335)
R335G "665" CR1608-0603 -2200,787.5 r90 bottom locked (schematic designator R335)
R335H "665" CR1608-0603 -2200,112.5 r90 bottom locked (schematic designator R335)
R335I "665" CR1608-0603 -2200,-562.5 r90 bottom locked (schematic designator R335)
R335J "665" CR1608-0603 -2200,-337.5 r90 bottom locked (schematic designator R335)
R335K "665" CR1608-0603 -2200,-112.5 r90 bottom locked (schematic designator R335)
R335L "665" CR1608-0603 -2200,-787.5 r90 bottom locked (schematic designator R335)
R335M "665" CR1608-0603 -2200,-1462.5 r90 bottom locked (schematic designator R335)
R335N "665" CR1608-0603 -2200,-1237.5 r90 bottom locked (schematic designator R335)
R335O "665" CR1608-0603 -2200,-1012.5 r90 bottom locked (schematic designator R335)
R335P "665" CR1608-0603 -2200,-1687.5 r90 bottom locked (schematic designator R335)
R351A "49.9" CR1005-0402 -2275,1287.5 r0 bottom locked (schematic designator R351)
R351B "49.9" CR1005-0402 -2275,1512.5 r0 bottom locked (schematic designator R351)
R351C "49.9" CR1005-0402 -2275,1737.5 r0 bottom locked (schematic designator R351)
R351D "49.9" CR1005-0402 -2275,1062.5 r0 bottom locked (schematic designator R351)
R351E "49.9" CR1005-0402 -2275,387.5 r0 bottom locked (schematic designator R351)
R351F "49.9" CR1005-0402 -2275,612.5 r0 bottom locked (schematic designator R351)
R351G "49.9" CR1005-0402 -2275,837.5 r0 bottom locked (schematic designator R351)
R351H "49.9" CR1005-0402 -2275,162.5 r0 bottom locked (schematic designator R351)
R351I "49.9" CR1005-0402 -2275,-512.5 r0 bottom locked (schematic designator R351)
R351J "49.9" CR1005-0402 -2275,-287.5 r0 bottom locked (schematic designator R351)
R351K "49.9" CR1005-0402 -2275,-62.5 r0 bottom locked (schematic designator R351)
R351L "49.9" CR1005-0402 -2275,-737.5 r0 bottom locked (schematic designator R351)
R351M "49.9" CR1005-0402 -2275,-1412.5 r0 bottom locked (schematic designator R351)
R351N "49.9" CR1005-0402 -2275,-1187.5 r0 bottom locked (schematic designator R351)
R351O "49.9" CR1005-0402 -2275,-962.5 r0 bottom locked (schematic designator R351)
R351P "49.9" CR1005-0402 -2275,-1637.5 r0 bottom locked (schematic designator R351)
R367A "49.9" CR1005-0402 -2250,1212.5 r270 bottom locked (schematic designator R367)
R367B "49.9" CR1005-0402 -2250,1437.5 r270 bottom locked (schematic designator R367)
R367C "49.9" CR1005-0402 -2250,1662.5 r270 bottom locked (schematic designator R367)
R367D "49.9" CR1005-0402 -2250,987.5 r270 bottom locked (schematic designator R367)
R367E "49.9" CR1005-0402 -2250,312.5 r270 bottom locked (schematic designator R367)
R367F "49.9" CR1005-0402 -2250,537.5 r270 bottom locked (schematic designator R367)
R367G "49.9" CR1005-0402 -2250,762.5 r270 bottom locked (schematic designator R367)
R367H "49.9" CR1005-0402 -2250,87.5 r270 bottom locked (schematic designator R367)
R367I "49.9" CR1005-0402 -2250,-587.5 r270 bottom locked (schematic designator R367)
R367J "49.9" CR1005-0402 -2250,-362.5 r270 bottom locked (schematic designator R367)
R367K "49.9" CR1005-0402 -2250,-137.5 r270 bottom locked (schematic designator R367)
R367L "49.9" CR1005-0402 -2250,-812.5 r270 bottom locked (schematic designator R367)
R367M "49.9" CR1005-0402 -2250,-1487.5 r270 bottom locked (schematic designator R367)
R367N "49.9" CR1005-0402 -2250,-1262.5 r270 bottom locked (schematic designator R367)
R367O "49.9" CR1005-0402 -2250,-1037.5 r270 bottom locked (schematic designator R367)
R367P "49.9" CR1005-0402 -2250,-1712.5 r270 bottom locked (schematic designator R367)
R383A "665" CR1608-0603 -2350,1287.5 r90 bottom locked (schematic designator R383)
R383B "665" CR1608-0603 -2350,1512.5 r90 bottom locked (schematic designator R383)
R383C "665" CR1608-0603 -2350,1737.5 r90 bottom locked (schematic designator R383)
R383D "665" CR1608-0603 -2350,1062.5 r90 bottom locked (schematic designator R383)
R383E "665" CR1608-0603 -2350,387.5 r90 bottom locked (schematic designator R383)
R383F "665" CR1608-0603 -2350,612.5 r90 bottom locked (schematic designator R383)
R383G "665" CR1608-0603 -2350,837.5 r90 bottom locked (schematic designator R383)
R383H "665" CR1608-0603 -2350,162.5 r90 bottom locked (schematic designator R383)
R383I "665" CR1608-0603 -2350,-512.5 r90 bottom locked (schematic designator R383)
R383J "665" CR1608-0603 -2350,-287.5 r90 bottom locked (schematic designator R383)
R383K "665" CR1608-0603 -2350,-62.5 r90 bottom locked (schematic designator R383)
R383L "665" CR1608-0603 -2350,-737.5 r90 bottom locked (schematic designator R383)
R383M "665" CR1608-0603 -2350,-1412.5 r90 bottom locked (schematic designator R383)
R383N "665" CR1608-0603 -2350,-1187.5 r90 bottom locked (schematic designator R383)
R383O "665" CR1608-0603 -2350,-962.5 r90 bottom locked (schematic designator R383)
R383P "665" CR1608-0603 -2350,-1637.5 r90 bottom locked (schematic designator R383)
R399A "665" CR1608-0603 -2600,1237.5 r90 bottom locked (schematic designator R399)
R399B "665" CR1608-0603 -2600,1462.5 r90 bottom locked (schematic designator R399)
R399C "665" CR1608-0603 -2600,1687.5 r90 bottom locked (schematic designator R399)
R399D "665" CR1608-0603 -2600,1012.5 r90 bottom locked (schematic designator R399)
R399E "665" CR1608-0603 -2600,337.5 r90 bottom locked (schematic designator R399)
R399F "665" CR1608-0603 -2600,562.5 r90 bottom locked (schematic designator R399)
R399G "665" CR1608-0603 -2600,787.5 r90 bottom locked (schematic designator R399)
R399H "665" CR1608-0603 -2600,112.5 r90 bottom locked (schematic designator R399)
R399I "665" CR1608-0603 -2600,-562.5 r90 bottom locked (schematic designator R399)
R399J "665" CR1608-0603 -2600,-337.5 r90 bottom locked (schematic designator R399)
R399K "665" CR1608-0603 -2600,-112.5 r90 bottom locked (schematic designator R399)
R399L "665" CR1608-0603 -2600,-787.5 r90 bottom locked (schematic designator R399)
R399M "665" CR1608-0603 -2600,-1462.5 r90 bottom locked (schematic designator R399)
R399N "665" CR1608-0603 -2600,-1237.5 r90 bottom locked (schematic designator R399)
R399O "665" CR1608-0603 -2600,-1012.5 r90 bottom locked (schematic designator R399)
R399P "665" CR1608-0603 -2600,-1687.5 r90 bottom (schematic designator R399)
R415A "49.9" CR1005-0402 -2675,1287.5 r0 bottom locked (schematic designator R415)
R415B "49.9" CR1005-0402 -2675,1512.5 r0 bottom locked (schematic designator R415)
R415C "49.9" CR1005-0402 -2675,1737.5 r0 bottom locked (schematic designator R415)
R415D "49.9" CR1005-0402 -2675,1062.5 r0 bottom locked (schematic designator R415)
R415E "49.9" CR1005-0402 -2675,387.5 r0 bottom locked (schematic designator R415)
R415F "49.9" CR1005-0402 -2675,612.5 r0 bottom locked (schematic designator R415)
R415G "49.9" CR1005-0402 -2675,837.5 r0 bottom locked (schematic designator R415)
R415H "49.9" CR1005-0402 -2675,162.5 r0 bottom locked (schematic designator R415)
R415I "49.9" CR1005-0402 -2675,-512.5 r0 bottom locked (schematic designator R415)
R415J "49.9" CR1005-0402 -2675,-287.5 r0 bottom locked (schematic designator R415)
R415K "49.9" CR1005-0402 -2675,-62.5 r0 bottom locked (schematic designator R415)
R415L "49.9" CR1005-0402 -2675,-737.5 r0 bottom locked (schematic designator R415)
R415M "49.9" CR1005-0402 -2675,-1412.5 r0 bottom locked (schematic designator R415)
R415N "49.9" CR1005-0402 -2675,-1187.5 r0 bottom locked (schematic designator R415)
R415O "49.9" CR1005-0402 -2675,-962.5 r0 bottom locked (schematic designator R415)
R415P "49.9" CR1005-0402 -2675,-1637.5 r0 bottom (schematic designator R415)
R431A "49.9" CR1005-0402 -2650,1212.5 r270 bottom locked (schematic designator R431)
R431B "49.9" CR1005-0402 -2650,1437.5 r270 bottom locked (schematic designator R431)
R431C "49.9" CR1005-0402 -2650,1662.5 r270 bottom locked (schematic designator R431)
R431D "49.9" CR1005-0402 -2650,987.5 r270 bottom locked (schematic designator R431)
R431E "49.9" CR1005-0402 -2650,312.5 r270 bottom locked (schematic designator R431)
R431F "49.9" CR1005-0402 -2650,537.5 r270 bottom locked (schematic designator R431)
R431G "49.9" CR1005-0402 -2650,762.5 r270 bottom locked (schematic designator R431)
R431H "49.9" CR1005-0402 -2650,87.5 r270 bottom locked (schematic designator R431)
R431I "49.9" CR1005-0402 -2650,-587.5 r270 bottom locked (schematic designator R431)
R431J "49.9" CR1005-0402 -2650,-362.5 r270 bottom locked (schematic designator R431)
R431K "49.9" CR1005-0402 -2650,-137.5 r270 bottom locked (schematic designator R431)
R431L "49.9" CR1005-0402 -2650,-812.5 r270 bottom locked (schematic designator R431)
R431M "49.9" CR1005-0402 -2650,-1487.5 r270 bottom locked (schematic designator R431)
R431N "49.9" CR1005-0402 -2650,-1262.5 r270 bottom locked (schematic designator R431)
R431O "49.9" CR1005-0402 -2650,-1037.5 r270 bottom locked (schematic designator R431)
R431P "49.9" CR1005-0402 -2650,-1712.5 r270 bottom locked (schematic designator R431)
R447A "665" CR1608-0603 -2750,1287.5 r90 bottom locked (schematic designator R447)
R447B "665" CR1608-0603 -2750,1512.5 r90 bottom locked (schematic designator R447)
R447C "665" CR1608-0603 -2750,1737.5 r90 bottom locked (schematic designator R447)
R447D "665" CR1608-0603 -2750,1062.5 r90 bottom locked (schematic designator R447)
R447E "665" CR1608-0603 -2750,387.5 r90 bottom locked (schematic designator R447)
R447F "665" CR1608-0603 -2750,612.5 r90 bottom locked (schematic designator R447)
R447G "665" CR1608-0603 -2750,837.5 r90 bottom locked (schematic designator R447)
R447H "665" CR1608-0603 -2750,162.5 r90 bottom locked (schematic designator R447)
R447I "665" CR1608-0603 -2750,-512.5 r90 bottom locked (schematic designator R447)
R447J "665" CR1608-0603 -2750,-287.5 r90 bottom locked (schematic designator R447)
R447K "665" CR1608-0603 -2750,-62.5 r90 bottom locked (schematic designator R447)
R447L "665" CR1608-0603 -2750,-737.5 r90 bottom locked (schematic designator R447)
R447M "665" CR1608-0603 -2750,-1412.5 r90 bottom locked (schematic designator R447)
R447N "665" CR1608-0603 -2750,-1187.5 r90 bottom locked (schematic designator R447)
R447O "665" CR1608-0603 -2750,-962.5 r90 bottom locked (schematic designator R447)
R447P "665" CR1608-0603 -2750,-1637.5 r90 bottom locked (schematic designator R447)
R500 "1.0k" CR1005-0402 1981.25,243.75 r270 top
S1 "SW DIP-8" DIP_SW_8WAY_SMD_SIDE 425,1625 r180 top locked
TP1 "Testpoint" TP1-RED -2975,-987.5 r90 top
TP2 "Testpoint" TP1-YLW#1 -2975,-787.5 r90 top
TP3 "Testpoint" TP1-YLW#1 -2975,-175 r90 top
TP4 "Testpoint" TP1-YLW#1 -62.5,-1562.5 r270 top
TP5 "Testpoint" TP1-RED 287.5,-1750 r90 top
TP6 "Testpoint" TP1-YLW#1 287.5,-1562.5 r270 top
TP7 "Testpoint" TP1-YLW#1 287.5,-1365 r270 top
TP8 "Testpoint" TP1-RED 850,1125 r180 top
TP9 "Testpoint" TP1-RED 1025,1125 r180 top
TP10 "Testpoint" TP1-RED 1025,1350 r180 top
TP11 "Testpoint" TP1-RED 1025,1575 r180 top
TP12 "Testpoint" TP1-BLK 1281.25,-925 r90 top
TP13 "Testpoint" TP1-BLK 1281.25,-712.5 r90 top
TP14 "Testpoint" TP1-BLK 1281.25,-512.5 r90 top
TP15 "Testpoint" TP1-RED 1312.5,-12.5 r90 top
TP16 "Testpoint" TP1-BLK 1350,1800 r180 top
TP17 "Testpoint" TP1-WHT 1450,-1550 r90 top
TP18 "Testpoint" TP1-RED 1450,-1075 r90 top
TP19 "Testpoint" TP1-RED 1450,-812.5 r90 top
TP20 "Testpoint" TP1-RED 1450,-612.5 r90 top
TP21 "Testpoint" TP1-RED 1450,-312.5 r90 top
TP22 "Testpoint" TP1-RED 1450,-12.5 r90 top
TP23 "Testpoint" TP1-BLK 1600,893.75 r90 top
TP24 "Testpoint" TP1-RED 1600,1800 r180 top
TP25 "Testpoint" TP1-RED 1850,893.75 r90 top
TP26 "Testpoint" TP1-YLW#2 1850,1801.97 r0 top
TP27 "Testpoint" TP1-RED 2312.5,1187.5 r180 top
TP28 "Testpoint" TP1-RED 2312.5,1800 r0 top
TP29 "Testpoint" TP1-RED 2437.5,1800 r0 top
TP30 "Testpoint" TP1-BLK 2562.5,1800 r180 top
TP31 "Testpoint" TP1-WHT 2743.75,-1718.75 r90 top
TP32 "Testpoint" TP1-BLK 2743.75,-1381.25 r90 top
TP33 "Testpoint" TP1-RED 2743.75,456.25 r90 top
TP34 "Testpoint" TP1-RED 2750,-843.75 r90 top
TP35 "Testpoint" TP1-RED 2750,-181.25 r90 top
TP36 "Testpoint" TP1-RED 3175,-937.5 r90 top
TP37 "Testpoint" TP1-RED 3175,-512.5 r90 top
TP38 "Testpoint" TP1-RED 3175,-87.5 r90 top
TP39 "Testpoint" TP2 -293.75,-1081.25 r270 bottom
TP40 "Testpoint" TP2 -293.75,-975 r270 bottom
TP41A "Testpoint" TP2 -1737.5,925 r270 bottom (schematic designator TP41)
TP41B "Testpoint" TP2 -1737.5,25 r270 bottom (schematic designator TP41)
TP41C "Testpoint" TP2 -1737.5,-875 r270 bottom (schematic designator TP41)
TP41D "Testpoint" TP2 -1737.5,-1775 r270 bottom (schematic designator TP41)
TP42 "Testpoint" TP1-BLK -2968.75,1687.5 r90 top
TP45A "Testpoint" TP2 -2025,1200 r180 bottom (schematic designator TP45)
TP45B "Testpoint" TP2 -2025,300 r180 bottom (schematic designator TP45)
TP45C "Testpoint" TP2 -2025,-612.5 r180 bottom (schematic designator TP45)
TP45D "Testpoint" TP2 -2025,-1500 r180 bottom (schematic designator TP45)
U1 "OP284FS" SO-8_N -2975,-468.75 r270 top
U2 "ADR4530" SO-G8 -2975,900 r180 top
U3A "OPA1612AID" D0008A_M -2675,1237.5 r0 top locked (schematic designator U3)
U3B "OPA1612AID" D0008A_M -2675,1462.5 r0 top locked (schematic designator U3)
U3C "OPA1612AID" D0008A_M -2675,1687.5 r0 top locked (schematic designator U3)
U3D "OPA1612AID" D0008A_M -2675,1012.5 r0 top locked (schematic designator U3)
U3E "OPA1612AID" D0008A_M -2675,337.5 r0 top locked (schematic designator U3)
U3F "OPA1612AID" D0008A_M -2675,562.5 r0 top locked (schematic designator U3)
U3G "OPA1612AID" D0008A_M -2675,787.5 r0 top locked (schematic designator U3)
U3H "OPA1612AID" D0008A_M -2675,112.5 r0 top locked (schematic designator U3)
U3I "OPA1612AID" D0008A_M -2675,-562.5 r0 top locked (schematic designator U3)
U3J "OPA1612AID" D0008A_M -2675,-337.5 r0 top locked (schematic designator U3)
U3K "OPA1612AID" D0008A_M -2675,-112.5 r0 top locked (schematic designator U3)
U3L "OPA1612AID" D0008A_M -2675,-787.5 r0 top locked (schematic designator U3)
U3M "OPA1612AID" D0008A_M -2675,-1462.5 r0 top locked (schematic designator U3)
U3N "OPA1612AID" D0008A_M -2675,-1237.5 r0 top locked (schematic designator U3)
U3O "OPA1612AID" D0008A_M -2675,-1012.5 r0 top locked (schematic designator U3)
U3P "OPA1612AID" D0008A_M -2675,-1687.5 r0 top locked (schematic designator U3)
U19A "OPA1612AID" D0008A_M -2275,1237.5 r0 top locked (schematic designator U19)
U19B "OPA1612AID" D0008A_M -2275,1462.5 r0 top locked (schematic designator U19)
U19C "OPA1612AID" D0008A_M -2275,1687.5 r0 top locked (schematic designator U19)
U19D "OPA1612AID" D0008A_M -2275,1012.5 r0 top locked (schematic designator U19)
U19E "OPA1612AID" D0008A_M -2275,337.5 r0 top locked (schematic designator U19)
